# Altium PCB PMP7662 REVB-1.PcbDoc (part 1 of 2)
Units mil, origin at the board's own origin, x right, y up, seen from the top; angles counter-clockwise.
Board outline 7874.02 x 3937.01 mil, 2 copper layers (Top Layer, Bottom Layer), stack 62 mil thick; 165 components, 77 nets, 359 pads, 90 vias.
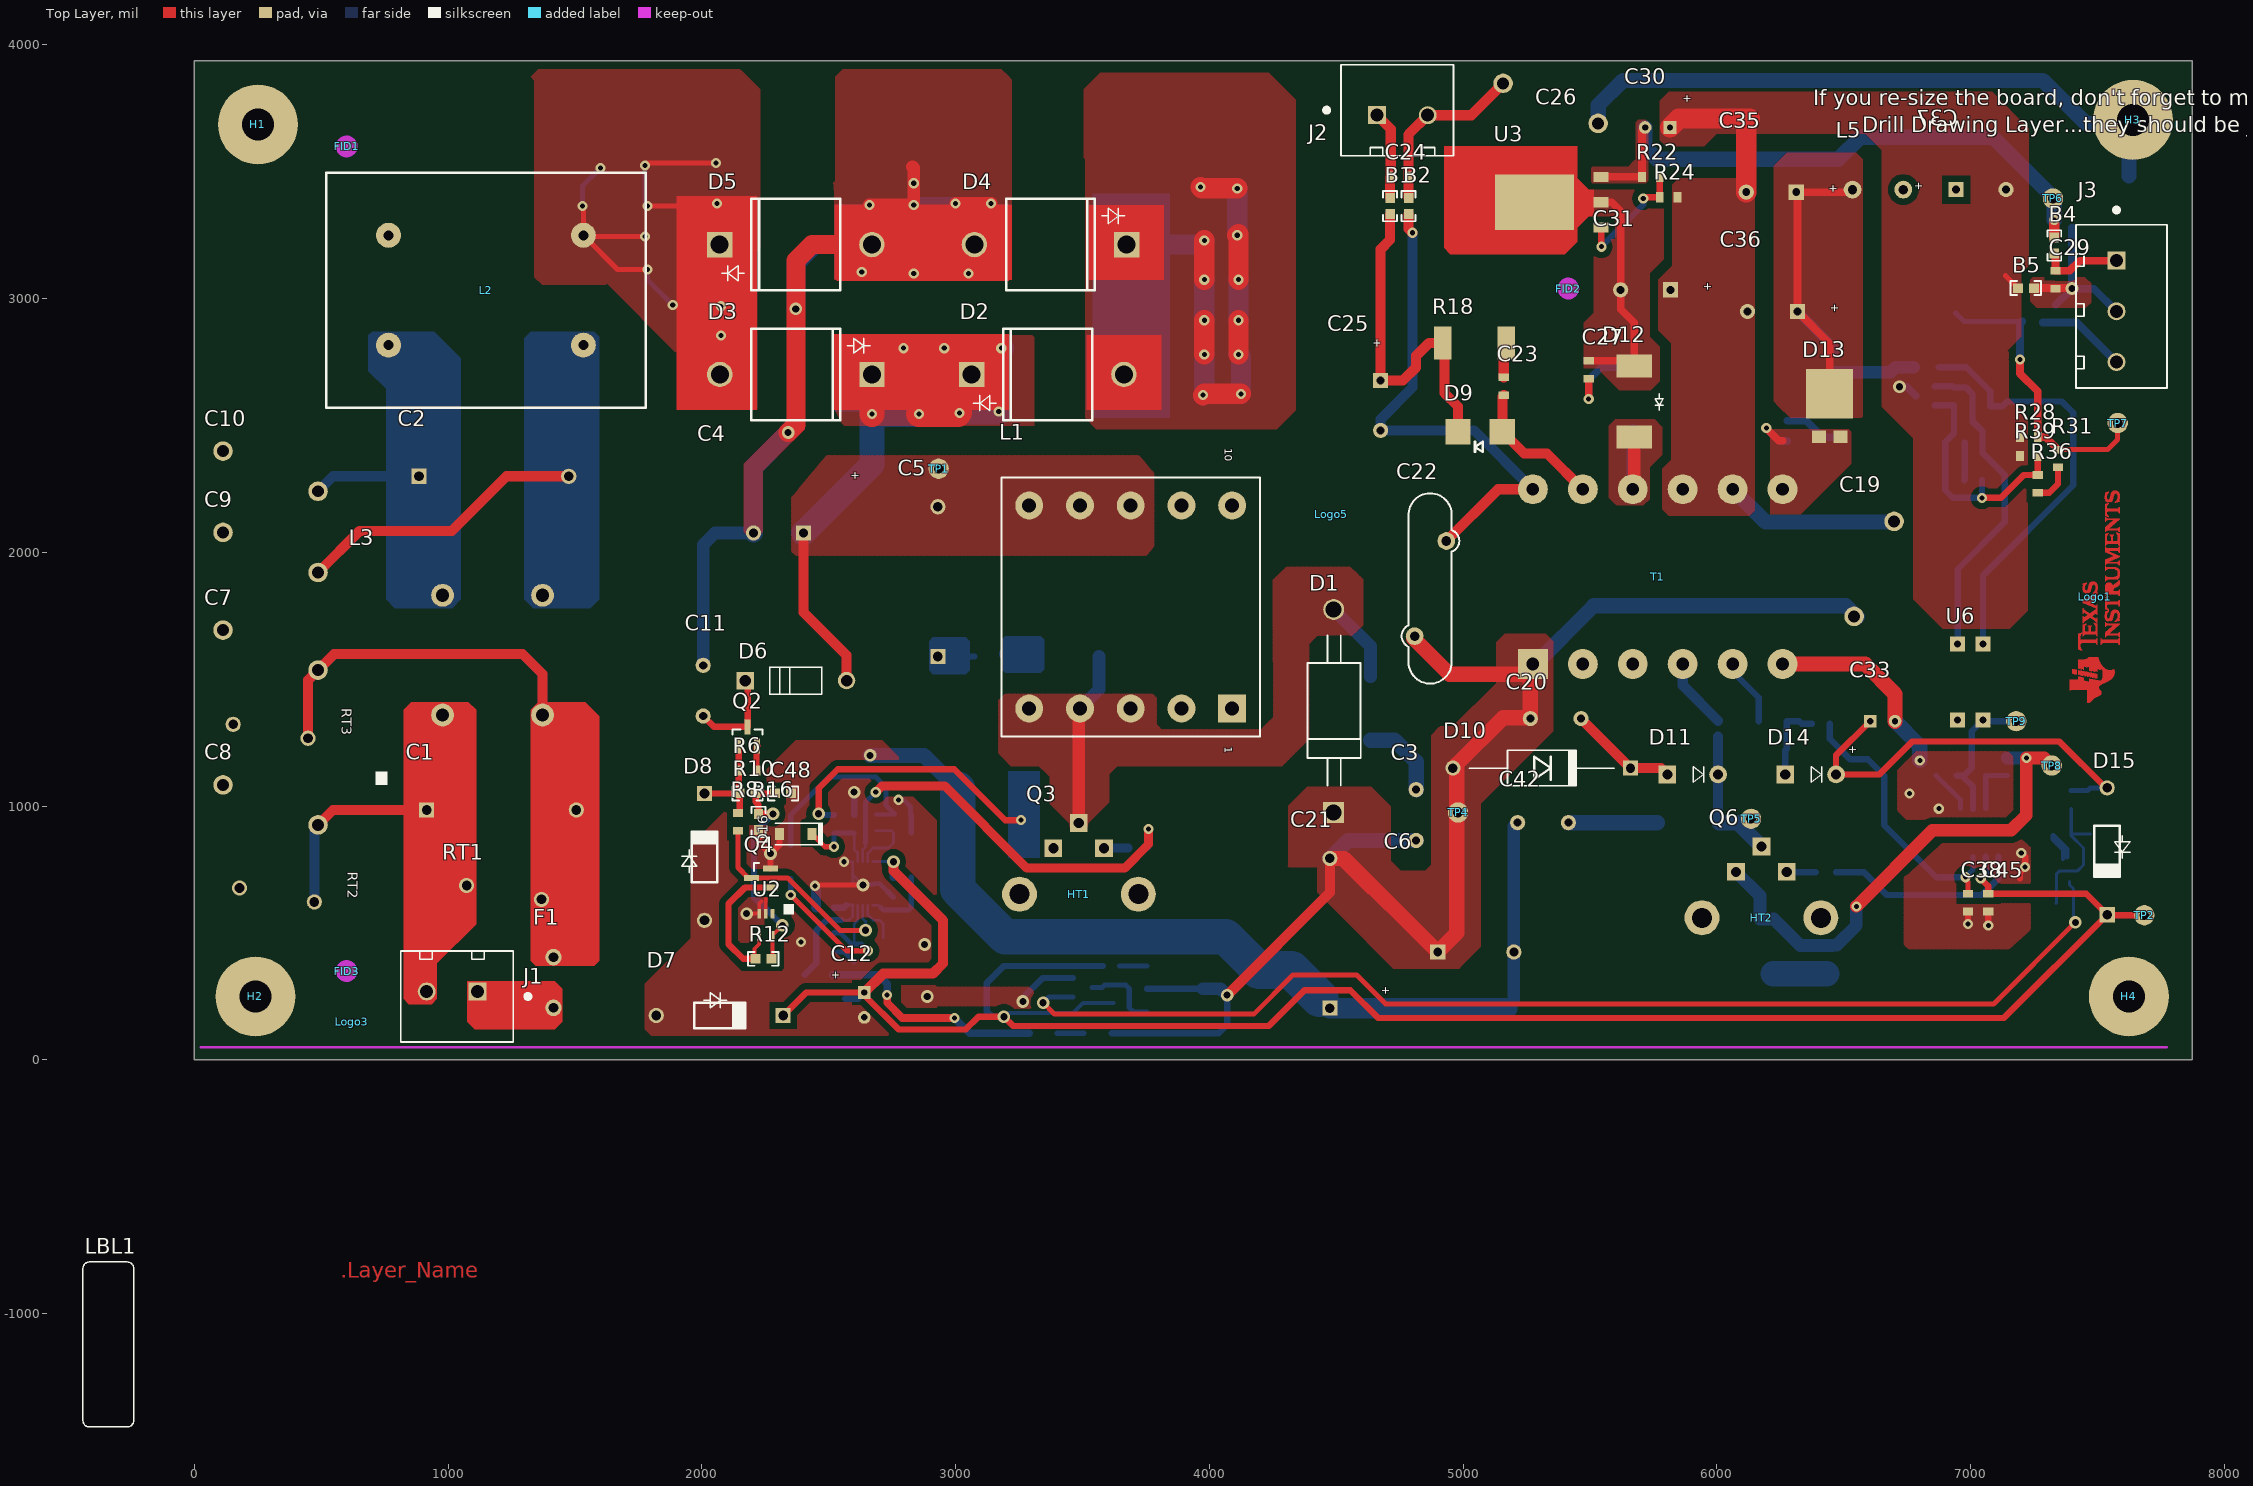
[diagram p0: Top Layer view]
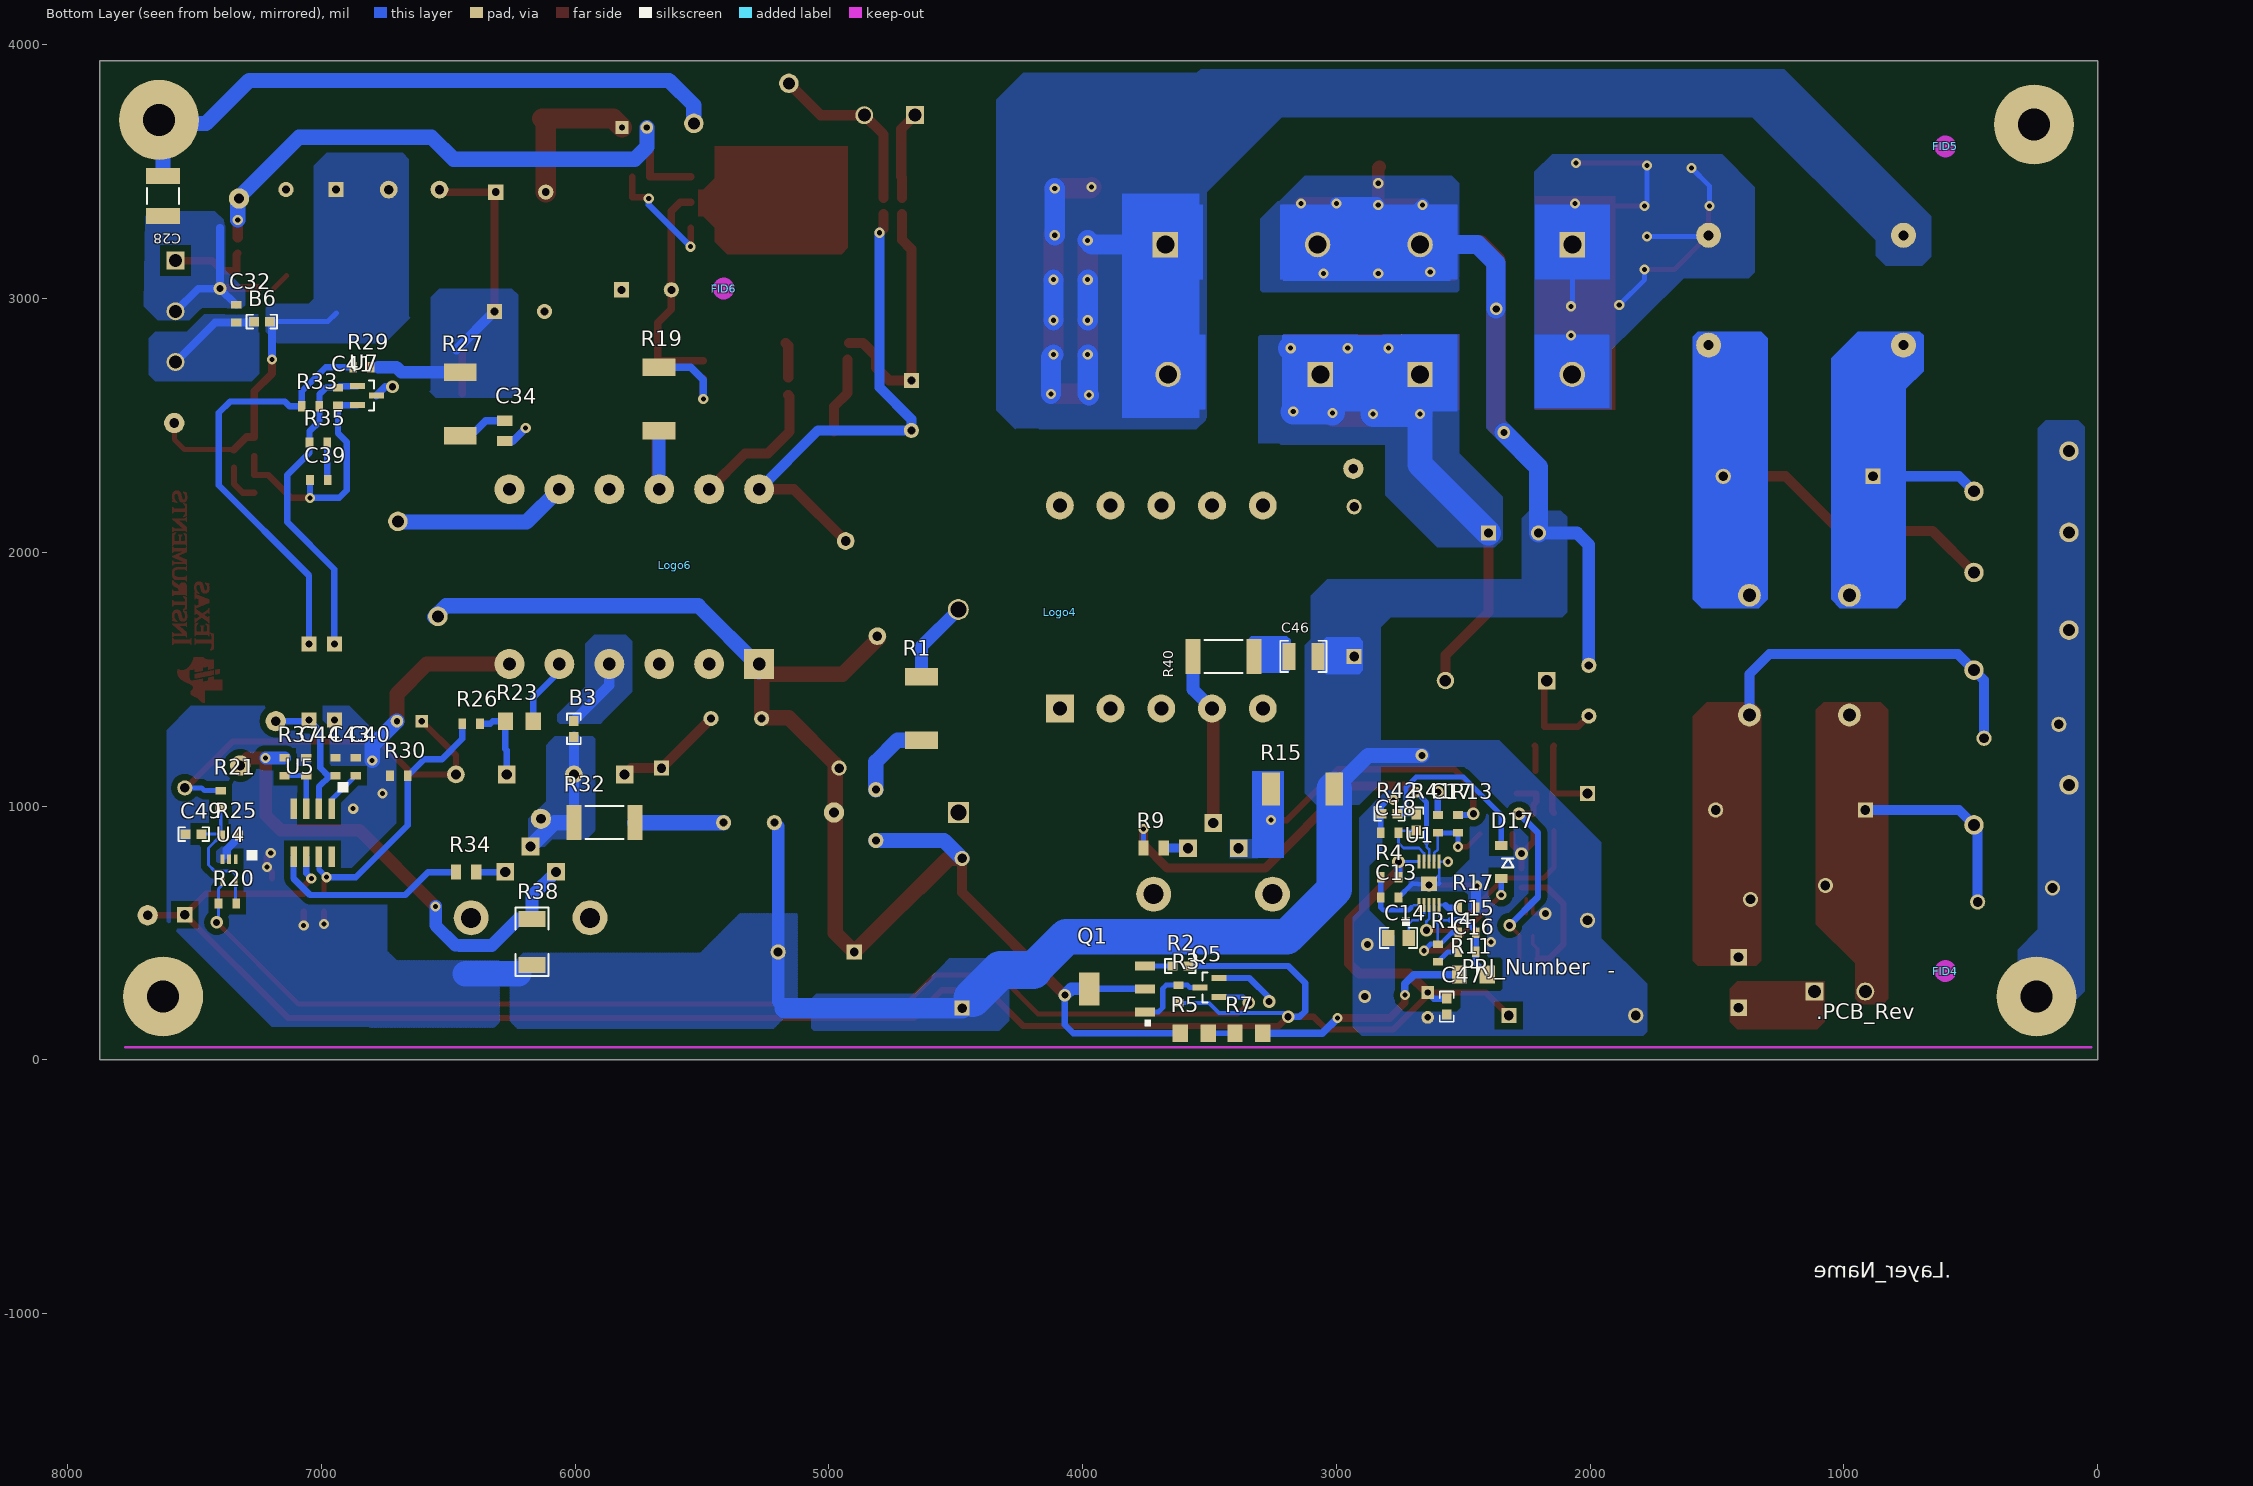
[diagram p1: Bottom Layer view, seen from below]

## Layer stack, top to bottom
Top Layer: signal copper 1.4
Dielectric: core 59.2, FR-4, Dk 4.8
Bottom Layer: signal copper 1.4

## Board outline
0,0 7874.02,0 7874.02,3937.01 0,3937.01

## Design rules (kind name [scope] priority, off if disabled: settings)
AcuteAngle [All] p1: minimum=4.50000000000000E+0001 checktracksonly=FALSE
AssemblyTestPointUsage [All] p1: valid=2
Clearance Clearance_TH [IsVia vs IsThruPin] p1: gap=15
Clearance "Clearance_SMT to Via" [IsSMTPin vs IsVia] p2: gap=15
Clearance "Clearance_Via to Via" [IsVia vs IsVia] p3: gap=12
Clearance "Clearance_Poly to Poly" [InPolygon vs InPolygon] p4: gap=25
Clearance Clearance_Poly [InPolygon] p5: gap=25
Clearance [All] p6: gap=8
ComponentClearance ComponentClearance_Logo [InComponentClass('Logo')] p1: gap=50 collisioncheckmode=3 verticalgap=10 showdistances=FALSE
ComponentClearance ComponentClearance_ScrewToNut [(HasFootprint('NY PMS 440 0025 PH')) vs (HasFootprint('Keystone_1902C'))] p2: gap=5 collisioncheckmode=3 verticalgap=10 showdistances=FALSE
ComponentClearance ComponentClearance_MountingHoles [InComponentClass('Mounting Holes')] p3: gap=250 collisioncheckmode=3 verticalgap=100000 showdistances=FALSE
ComponentClearance ComponentClearance_SmallPassives [HasFootprint('0201*') or HasFootprint('0402*') or HasFootprint('0508') or HasFootprint('0603*') or HasFootprint('0612') or HasFootprint('0805*') or HasFootprint('0815*') or HasFootprint('0830*') or HasFootprint('1206*') or HasFootprint('1210*') or HasFootprint('1808*') or HasFootprint('1812*') or HasFootprint('1825*') or HasFootprint('2010*') or HasFootprint('2220*') or HasFootprint('2225*') or HasFootprint('2512*') or HasFootprint('2728*') or HasFootprint('3518*') vs HasFootprint('0201*') or HasFootprint('0402*') or HasFootprint('0508') or HasFootprint('0603*') or HasFootprint('0612') or HasFootprint('0805*') or HasFootprint('0815*') or HasFootprint('0830*') or HasFootprint('1206*') or HasFootprint('1210*') or HasFootprint('1808*') or HasFootprint('1812*') or HasFootprint('1825*') or HasFootprint('2010*') or HasFootprint('2220*') or HasFootprint('2225*') or HasFootprint('2512*') or HasFootprint('2728*') or HasFootprint('3518*')] p4: gap=20 collisioncheckmode=3 verticalgap=10 showdistances=FALSE
ComponentClearance ComponentClearance_THtoSMT [IsThruComponent vs IsSMTComponent] p5: gap=100 collisioncheckmode=3 verticalgap=30 showdistances=FALSE
ComponentClearance ComponentClearance_THtoTH [IsThruComponent vs IsThruComponent] p6: gap=118.11 collisioncheckmode=3 verticalgap=30 showdistances=FALSE
ComponentClearance [All] p7: gap=40 collisioncheckmode=3 verticalgap=10 showdistances=FALSE
DiffPairsRouting [All] p1: maxlimit=100 minlimit=10 mostfreqgap=10 maxuncoupledlength=1000
FabricationTestPointUsage TestPointUsage [All] p1: valid=2 allowmultiple=FALSE
FabricationTestpoint Testpoint [All] p1: side=3 testpointundercomponent=TRUE minsize=40 maxsize=100 preferedsize=60 minholesize=0 maxholesize=40 preferedholesize=32 testpointgrid=1 allowsidetop=TRUE allowsidebottom=TRUE usegrid=TRUE gridtolerance=0.01
FanoutControl Fanout_LCC [IsLCC] p1: bgadir=Out bgaviamode=Centered fanoutstyle=Auto fanoutdirection=Alternating viagrid=1 // Fanout_LCC (Default Rule)
FanoutControl Fanout_BGA [IsBGA] p2: bgadir=Out bgaviamode=Centered fanoutstyle=Auto fanoutdirection=Alternating viagrid=1 // Fanout_BGA (Default Rule)
FanoutControl Fanout_Default [All] p4: bgadir=Out bgaviamode=Centered fanoutstyle=Auto fanoutdirection=Alternating viagrid=1 // Fanout_Default (Default Rule)
FanoutControl Fanout_Small [(CompPinCount < 5)] p5: bgadir=Out bgaviamode=Centered fanoutstyle=Auto fanoutdirection=OutThenIn viagrid=1 // Fanout_Small (Default Rule)
HoleSize [All] p1: absolutevalues=TRUE maxlimit=251 minlimit=8 maxpercent=80.000 minpercent=20.000
MinimumAnnularRing MinimumAnnularRing_ThermalPadVias [IsVia and InAnyComponent] p1: minimumring=5.91
MinimumAnnularRing [All] p2: minimumring=9
MinimumSolderMaskSliver MinimumSolderMaskSliver_Logo [InComponentClass('Logo') vs InComponentClass('Logo')] p1: minsoldermaskwidth=0.7
MinimumSolderMaskSliver [All] p2: minsoldermaskwidth=3.94
PlaneConnect [All] p1: planeconnectstyle=Relief reliefexpansion=10 reliefentries=4 reliefconductorwidth=10 reliefairgap=10
PolygonConnect [All] p1: connectstyle=Direct reliefconductorwidth=20 reliefentries=4 polygonreliefangle="45 Angle" airgapwidth=10
RoomDefinition Hardware [InComponentClass('Hardware')] p1: confinementstyle=ConfineIn formatcopy=TRUE lockcomponents=FALSE outline -692,-1534 1308,-1534 1308,-534 -692,-534
RoomDefinition "Fly back converter" [InComponentClass('Fly back converter')] p2: confinementstyle=ConfineIn formatcopy=TRUE lockcomponents=FALSE outline -692,-1534 1308,-1534 1308,-534 -692,-534
RoomDefinition "Boost converter" [InComponentClass('Boost converter')] p3: confinementstyle=ConfineIn formatcopy=TRUE lockcomponents=FALSE outline -692,-1534 1308,-1534 1308,-534 -692,-534
RoutingVias ThermalPadVias [IsVia and InAnyComponent] p1: holewidth=20 width=40 viastyle="Through Hole" minholewidth=16 minwidth=30 maxholewidth=20 maxwidth=40
RoutingVias [All] p2: holewidth=20 width=40 viastyle="Through Hole" minholewidth=20 minwidth=40 maxholewidth=40 maxwidth=65
SMDToCorner [All] p1: distance=30000
SilkToSilkClearance [All] p1: silktosilkclearance=5
SilkscreenOverComponentPads [All] p1: minsilkscreentomaskgap=5
SolderMaskExpansion [All] p1: expansion=2
Width [All] p1: maxlimit=200 minlimit=10 preferedwidth=20 checkconnectedcopper=TRUE
14 further rules are at their usual default settings.

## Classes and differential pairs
component class hardware: !PCB1 FID1 FID2 FID3 FID4 FID5 FID6 H1 H2 H3 H4 LBL1 Logo1
component class "Boost converter": C1 C2 C3 C4 C5 C6 C7 C8 C9 C10 C11 C12 C13 C14 C15 C16 C17 C18 C46 C47 C48 D1 D2 D3 D4 D5 D6 D7 D8 D16 D17 F1 HT1 J1 L1 L2 L3 Q1 Q2 Q3 Q4 R1 R2 R3 R4 R5 R6 R7 R8 R9 R10 R11 R12 R13 R14 R15 R16 R17 R40 R41 R42 RT1 RT2 RT3 TP1 TP2 U1 U2
component class "Fly back converter": B1 B2 B3 B4 B5 B6 C19 C20 C21 C22 C23 C24 C25 C26 C27 C28 C29 C30 C31 C32 C33 C34 C35 C36 C37 C38 C39 C40 C41 C42 C43 C44 C45 C49 D9 D10 D11 D12 D13 D14 D15 HT2 J2 J3 J7 J8 J9 L5 Q5 Q6 R18 R19 R20 R21 R22 R23 R24 R25 R26 R27 R28 R29 R30 R31 R32 R33 R34 R35 R36 R37 R38 R39 T1 TP4 TP5 TP6 TP7 TP8 TP9 U3 U4 U5 U6 U7

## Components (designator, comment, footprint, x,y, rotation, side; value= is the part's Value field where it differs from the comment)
B1 "BEAD-BLM18AG_SERIES" 0603 4712,3365 r90 top
B2 "BEAD-BLM18AG_SERIES" 0603 4785,3365 r90 top
B3 "CIS10P700AC" 0603 6005,1305 r90 bottom
B4 "BEAD-BLM18AG_SERIES" 0603 7330,3210 r270 top
B5 "BEAD-BLM18AG_SERIES" 0603 7218,3042 r0 top
B6 "BEAD-BLM18AG_SERIES" 0603 7235,2910 r0 bottom
C1 "R46KI347050P1M" CAP_591MIL 915,985 r0 top
C2 "R46KI347050P1M" CAP_591MIL 885,2300 r0 top
C3 "CAP_DE2B3K_7MM_SERIES" CAP_200MIL-A 4815,965 r90 top
C4 "CAP_EEU-FC1E16_20MM" CAP_16MM_DIA_ 2300,2080 r270 top
C5 "R46KI347050P1M" CAP_591MIL 2930,1590 r90 top
C6 "CAP_EEU-FC18_25MM" CAP_EEUFC1H 5055,425 r90 top
C7 "CAP_DISK_440_[8.4MM]" CAP_DISK_8.4MM 300,1615 r180 top
C8 "CAP_DISK_440_[8.4MM]" CAP_DISK_8.4MM 300,1005 r180 top
C9 "VY2222M35Y5US63V7" CAP_DISK_8.4MM 300,2000 r180 top
C10 "VY2222M35Y5US63V7" CAP_DISK_8.4MM 300,2320 r180 top
C11 "CAP_ECU-S1HXXKBB" CAP_200MIL 2005,1455 r270 top
C12 "CAP_ZL_6.3MM_SERIES" CAP_ZL-6.3MM 2640,215 r0 top
C13 "C603" C603 2790,640 r0 bottom
C14 "C2012X5R1C226K125AC" 0805_HV 2755,481 r0 bottom
C15 "C603" C603 2485,501 r0 bottom
C16 "C603" C603 2485,426 r180 bottom
C17 "C603" C603 2600,930 r270 bottom
C18 "C603" C603 2790,895 r180 bottom
C19 "VY2222M35Y5US63V7" CAP_DISK_8.4MM 6620,1935 r90 top
C20 "CAP_ECU-S1HXXKBB" CAP_200MIL 5365,1345 r180 top
C21 "R46KI347050P1M" CAP_591MIL 4475,204 r90 top
C22 "CAP_DISK_720" CAP_DISK_720 4935,2045 r270 top
C23 "C603" c603 5160,2655 r90 top
C24 "C603" C603 4750,3481 r0 top
C25 "CAP_EKZE_10MM_SERIES" CAP_ALUM-10MM#1 4675,2680 r0 top
C26 "VY2222M35Y5US63V7" CAP_DISK_8.4MM 5345,3770 r0 top
C27 "C603" C603 5495,2720 r270 top
C28 "1812GC472KAT1A" 1812 7625,3405 r270 bottom
C29 "C603" C603 7335,3075 r270 top
C30 "CAP_ZL_6.3MM_SERIES" CAP_ZL-6.3MM 5765,3675 r270 top
C31 "CAP_EKZE_10MM_SERIES" CAP_ALUM-10MM#1 5820,3035 r270 top
C32 "C603" C603 7336,2941 r270 bottom
C33 "CAP_ZL_6.3MM_SERIES" CAP_ZL-6.3MM 6655,1335 r90 top
C34 "C0805" C0805 6278,2479 r270 bottom
C35 "CAP_EKZE_10MM_SERIES" CAP_ALUM-10MM#1 6315,3420 r270 top
C36 "CAP_EKZE_10MM_SERIES" CAP_ALUM-10MM#1 6320,2950 r270 top
C37 "CAP_ALUM_FC-F" CAP_ALUM-10MM#2 6941,3430 r270 top
C38 "C603" C603 6990,620 r270 top
C39 "C603" C603 7010,2285 r180 bottom
C40 "C603" c603 6865,1155 r270 bottom
C41 "C603" C603 6935,2614 r270 bottom
C42 "CAP_DE2B3K_7MM_SERIES" CAP_200MIL-A 5315,935 r180 top
C43 "C603" c603 6945,1155 r90 bottom
C44 "C603" c603 7060,1155 r90 bottom
C45 "C603" c603 7070,620 r90 top
C46 "GRM32QR73A103KW01L" 1210 3130,1590 r180 bottom
C47 "GRM188R71C683KA01D" 0603 2565,210 r270 bottom
C48 "GRM188R71C683KA01D" 0603 2320,1050 r0 top
C49 "GRM188R71C683KA01D" 0603 7503.5,890 r0 bottom
D1 "D-MUR4XX_SERIES" DO-201AD 4490,1375 r90 top
D2 "D-6A0X" R-6 3063,2701.5 r0 top
D3 "D-6A0X" R-6 2670.32,2701.5 r180 top
D4 "D-6A0X" R-6 3674,3213.31 r180 top
D5 "D-6A0X" R-6 2070,3213.31 r0 top
D6 "D-1N4006" DO-41 2370,1495 r0 top
D7 "D-1N52XXB" DO-35 2320,175 r180 top
D8 "D-1N52XXB" DO-35 2010,1050 r270 top
D9 "D_SCHOT_SMB" MOT_SMB_CASE 5067,2476 r0 top
D10 "D_P6KEXXX" DO-204AC 5310,1150 r180 top
D11 "D-1N4006" DO-41_VERT 5805,1125 r0 top
D12 "D-ES3D" DO-214AB 5675,2595 r90 top
D13 "D-S4P_SERIES" TO-277[SMPC] 6445,2625 r0 top
D14 "D-1N4006" DO-41_VERT 6270,1125 r0 top
D15 "D-1N4148MSCT" DO-35 7538.5,572 r90 top
D16 "1N5819HW-7-F" SOD-123 2370,890 r180 top
D17 "D-1N4148-7-F" D_SOD123 2350,780 r90 bottom
F1 "FUSE_RST_SERIES" FUSE_4X8.5-5.08P 1415,205 r90 top
FID1 "Fiducial" Fiducial10-20 600,3600 r0 top
FID2 "Fiducial" Fiducial10-20 5415,3040 r0 top
FID3 "Fiducial" Fiducial10-20 600,350 r0 top
FID4 "Fiducial" Fiducial10-20 600,350 r180 bottom
FID5 "Fiducial" Fiducial10-20 600,3600 r180 bottom
FID6 "Fiducial" Fiducial10-20 5415,3040 r180 bottom
H1 "" "NY PMS 440 0025 PH" 250,3687.01 r0 top locked
H2 "" "NY PMS 440 0025 PH" 240,250 r90 top
H3 "" "NY PMS 440 0025 PH" 7640,3705 r90 top
H4 "" "NY PMS 440 0025 PH" 7624.02,250 r0 top locked
HT1 "HEATSINK_PMP1445-HS4" R2A-CT2-38E-ND 3720,653 r180 top
HT2 "HEATSINK_PMP1445-HS4" R2A-CT2-38E-ND 6410,560 r180 top locked
J1 "OSTTA024163" On-Shore_OSTTA024163 1035,250 r180 top
J2 "OSTTA024163" On-Shore_OSTTA024163 4741,3743 r0 top
J3 "OSTTA034163" On-Shore_OSTTA034163 7595,2970 r270 top
L1 "IND_EF25_10P" IND_EF25_10P 4090,1385 r270 top
L2 "SS30V-R350047" SS30V 765,3250 r0 top
L3 "1.0mH" IND_WE_728_X_1083 1175,1595 r90 top
L5 "2.2uH" IND_200_MIL 6635,3430 r0 top
LBL1 "" Label_650x200 -339.5,-1121.5 r90 top
Logo1 "" TI_Stacked_SolderMask_Small 7490,1825 r90 top
Logo3 "DANGER HIGH VOLTAGE" IEC_HighVoltage_Small 620,150 r0 top
Logo4 "DANGER HIGH VOLTAGE" IEC_HighVoltage_Small 4090,1765 r180 bottom (schematic designator Logo3)
Logo5 "DANGER HIGH VOLTAGE" IEC_HighVoltage_Small 4480,2150 r0 top (schematic designator Logo3)
Logo6 "DANGER HIGH VOLTAGE" IEC_HighVoltage_Small 5607.88,1950 r180 bottom (schematic designator Logo3)
Q1 "TR_NFET_SOT223" TR_SOT223 3865,280 r90 bottom
Q2 "TR-BSS126" SOT-23 2180,1275 r90 top
Q3 "TR-FQPF2N60C" TO-220V 3585,834.1 r180 top locked
Q4 "TR-2N7002" SOT-23 2233,717 r180 top
Q5 "TR-2N7002" SOT-23 3500,285 r0 bottom
Q6 "TR-FQPF2N60C" TO-220V 6275.75,741.1 r180 top
R1 "R2512" R2512 4635,1385 r270 bottom
R2 "RC0603FR-07220RL" 0603 3615,370 r0 bottom
R3 "R603" R603 3621.57,259.3 r270 bottom
R4 "R603" R603 2790,720 r0 bottom
R5 "R1206" R1206 3560,105 r180 bottom
R6 "R603" R603 2180,1140 r180 top
R7 "R1206" R1206 3345,105 r180 bottom
R8 "R603" R603 2142,938 r270 top
R9 "R0805_1%" R0805 3720,835 r180 bottom
R10 "CRCW0603402KFKEA" 0603 2180,1050 r0 top
R11 "R1206" r1206 2460,336 r180 bottom
R12 "CRCW06031M00FKEA" 0603 2242,398 r180 top
R13 "R603" R603 2520,930 r90 bottom
R14 "R603" R603 2600,421 r270 bottom
R15 "R2512_1%" R2512 3133,1067 r180 bottom
R16 "CRCW0603127KFKEA" 0603 2223,938 r270 top
R17 "R603" R603 2485,600 r180 bottom
R18 "R2512" R2512 5045,2825 r180 top
R19 "R2512" R2512 5670,2605 r270 bottom
R20 "R603" r603 7371,617 r0 bottom
R21 "R603" r603 7397,1026 r90 bottom
R22 "R603" R603 5740,3480 r180 top
R23 "R1206" R1206 6220,1335 r0 bottom
R24 "R603" R603 5810,3400 r0 top
R25 "R603" r603 7360,885 r180 bottom
R26 "R603" r603 6410,1325 r0 bottom
R27 "R2512" R2512 6453,2585 r90 bottom
R28 "R603" R603 7230,2455 r180 top
R29 "R603" R603 6840,2730 r180 bottom
R30 "R603" r603 6695,1120 r0 bottom
R31 "R603" R603 7345,2370 r90 top
R32 "CRCW2512162RFKEGHP" 2512M 5885,935 r0 bottom
R33 "R603" R603 7043,2576 r180 bottom
R34 "R0805_1%" r0805 6430,740 r180 bottom
R35 "R603" R603 7012,2433 r180 bottom
R36 "R603" R603 7265,2270 r90 top
R37 "R603" r603 7145,1155 r90 bottom
R38 "R2010" 2010 6170,465 r270 bottom
R39 "R603" R603 7230,2380 r180 top
R40 "RHC2512FT68R0" 2512M 3445,1590 r0 bottom
R41 "RC0603FR-0727KL" 0603 2685,935 r270 bottom
R42 "RC0603FR-074K3L" 0603 2790,970 r180 bottom
RT1 "MOV_B72210SXXXXK101" DISK-472 1220,660 r0 top
RT2 "MOV_B72210SXXXXK101" DISK-472 325,650 r0 top
RT3 "MOV_B72210SXXXXK101" DISK-472 300,1295 r0 top
T1 "EI-30" XFMR-EI30-10PIN-VER-TEMP 5275,1560 r90 top
TP1 "TESTPOINT" TESTPOINT 2933,2330 r0 top
TP2 "TESTPOINT" TESTPOINT 7685,570 r0 top
TP4 "TESTPOINT" TESTPOINT 4980,975 r0 top
TP5 "TESTPOINT" TESTPOINT 6135,950 r0 top
TP6 "TESTPOINT" TESTPOINT 7325,3395 r0 top
TP7 "TESTPOINT" TESTPOINT 7580,2510 r0 top
TP8 "TESTPOINT" TESTPOINT 7320,1160 r0 top
TP9 "TESTPOINT" TESTPOINT 7180,1335 r0 top
U1 "TPS40210DGQ" DGQ_10PWP 2634.8,694.5 r90 bottom
U2 "LMS33460" SC-70-5 2252,533 r180 top
U3 "LM337KTER" KTE 5280,3380 r90 top
U4 "LMS33460" SC-70-5 7364,747 r0 bottom
U5 "UCC28600DR" SO8 7035,895 r270 bottom
U6 "LTV-817A" DIP-4A 7050,1640 r270 top
U7 "TL431AIDBZ" SOT-23 6821,2618 r180 bottom

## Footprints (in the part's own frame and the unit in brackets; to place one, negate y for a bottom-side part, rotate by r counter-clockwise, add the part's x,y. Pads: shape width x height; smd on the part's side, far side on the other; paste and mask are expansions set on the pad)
0603 [mm] "0603 from SM-752 data"
  rect 1x0.95 smd: 1(-0.8,0) 2(0.8,0)
  silkscreen extent -1.52,-0.69 1.52,0.69, body extent -0.87,-0.47 0.87,0.47, height 0.85
0805_HV [mil] "0805 with 30mil clearance between pads"
  rect 50x63 smd: 1(-40,0) 2(40,0)
  silkscreen extent -74,-40 74,40, body extent -43,-29 43,29, height 43
1210 [mm] "1210 from SM-752 data"
  rect 1.3x2.7 smd: 1(-1.45,0) 2(1.45,0)
  silkscreen extent -2.32,-1.57 2.32,1.57, body extent -1.7,-1.35 1.7,1.35, height 1.35
1812 [mm]
  rect 1.6x3.4 smd: 1(-2,0) 2(2,0)
  silkscreen extent -0.8,-1.6 0.8,1.6, body extent -2.4,-1.7 2.4,1.7, height 1.35
2010 [mm] "Chip Capacitor, Body 5.08x2.54mm, IPC Medium Density"
  rect 1.6x2.7 smd: 1(-2.3,0) 2(2.3,0)
  silkscreen extent -3.42,-1.65 3.42,1.65, body extent -2.73,-1.45 2.73,1.45, height 1.66
2512M [mm] "Chip Resistor, Body 6.3x3.2mm, IPC Low Density"
  rect 1.5x3.5 smd: 1(-3.05,0) 2(3.05,0)
  silkscreen extent -1.9,-1.65 1.9,1.65, body extent -3.22,-1.67 3.22,1.67, height 0.71
C603 [mil]
  rect 30x40 smd mask+2: 1(-35,0) 2(35,0)
c603 [mil]
  rect 30x40 smd mask+2: 1(-35,0) 2(35,0)
C0805 [mil]
  rect 40x60 smd: 1(-40,0) 2(40,0)
CAP_16MM_DIA_ [mil]
  rect 60x60 hole 35 mask+5: 1(3.4,100.6)
  round 60 hole 35 mask+5: 2(3.4,-96.4)
CAP_200MIL [mil]
  round 60 hole 32 mask+5: 1(-100,0) 2(100,0)
CAP_200MIL-A [mil]
  round 60 hole 32: 1(-100,0) 2(100,0)
CAP_591MIL [mil]
  rect 60x60 hole 38: 1(0,0)
  round 60 hole 38: 2(590,0)
CAP_ALUM-10MM#1 [mil]
  rect 60x60 hole 31: 1(0,-2)
  round 60 hole 31: 2(0,-199)
CAP_ALUM-10MM#2 [mil]
  rect 60x60 hole 31: 1(0,2)
  round 60 hole 31: 2(0,199)
CAP_DISK_8.4MM [mil]
  round 77 hole 47: 1(-187,79) 2(187.5,-79)
CAP_DISK_720 [mil]
  round 70 hole 38: 1(0,-1) 2(375,-126)
  silkscreen extent -188,-177 562,50
CAP_EEUFC1H [mil]
  rect 60x60 hole 35: 1(0.1,155)
  round 60 hole 35: 2(0,-145)
CAP_ZL-6.3MM [mil]
  rect 50x50 hole 25: 1(0,50.5)
  round 50 hole 25: 2(0,-47.5)
D_SOD123 [mil]
  rect 36x48 smd: 1(65,0) 2(-65,0)
  silkscreen extent -21,-48 14,-3
DGQ_10PWP [mil]
  rect 55x11 smd: 1(-84.5,39) 2(-84.5,19.3) 3(-84.5,-0.4) 4(-84.5,-20.1) 5(-84.5,-39.8) 6(86.5,-39.8) 7(86.5,-20.1) 8(86.5,-0.4) 9(86.5,19.3) 10(86.5,39)
  rect 57.87x61.81 smd: 11(0,0)
  silkscreen extent -165,75 -135,105
DIP-4A [mil]
  rect 60x60 hole 28: 1(0.5,-1) 2(0.5,-101) 3(300.5,-101) 4(300.5,-1)
DISK-472 [mil]
  round 60 hole 38: 1(-147.5,27.5) 2(147.5,-27.5)
DO-35 [mil]
  rect 60x60 hole 38: 1(0,0)
  round 60 hole 38: 2(500,0)
  silkscreen extent 150,-90 350,51
DO-41 [mm] "diode"
  rect 1.75x1.75 hole 1.15: 1(-5.08,0)
  round 1.75 hole 1.15: 2(5.08,0)
  silkscreen extent -2.62,-1.37 2.59,1.35, body extent -5.51,-1.36 5.51,1.36, height 2.72
DO-41_VERT [mil]
  rect 70x70 hole 40: 1(0,0)
  round 70 hole 40: 2(200,0)
  silkscreen extent 103,-30 143,30
DO-201AD [mm] "Vishay dimensions"
  rect 2.1x2.1 hole 1.6: 1(-10.16,0)
  round 2.1 hole 1.6: 2(10.16,0)
  silkscreen extent -7.47,-2.7 7.57,2.61, body extent -10.82,-2.68 10.82,2.61, height 5.3
DO-204AC [mil]
  rect 60x60 hole 37: 1(-350,0)
  round 60 hole 37: 2(350,0)
  silkscreen extent -285,-70 285,70
DO-214AB [mil]
  rect 90x140 smd: 1(-140,0) 2(140,0)
  silkscreen extent -35,-113 30,-83
Fiducial10-20 [mm]
  round 1 smd paste+0 mask+0.5: 1(0,0)
  Top Layer keep-out circle w1.178: c0,0 r0.5
FUSE_4X8.5-5.08P [mil]
  round 65 / inner rect 65x65 / far side rect 65x65 hole 38: 1(0,0) 2(200,0)
IEC_HighVoltage_Small [mil]
IND_200_MIL [mil]
  round 70 hole 37: 1(-100,0) 2(100,0)
IND_EF25_10P [mil]
  rect 110x110 hole 55: 1(0,0)
  round 110 hole 55: 2(0,-200) 3(0,-400) 4(0,-600) 5(0,-800) 6(-800,-800) 7(-800,-600) 8(-800,-400) 9(-800,-200) 10(-800,0)
  silkscreen extent -910,-910 110,110
IND_WE_728_X_1083 [mil]
  round 90 hole 52: 2(-236,197) 4(-236,-197) 7(236,-197) 9(236,197)
  silkscreen extent -510,415 -460,460
KTE [mil]
  rect 40x60 smd: 1(-100,-264) 2(0,-264) 3(100,-264)
  rect 220x310 smd: 4(0,-1.7)
Label_650x200 [mil] "Thermal Transfer Label"
  round 1 on Mech13: 0(0,0)
  silkscreen extent -325,-100 325,100, body extent -326,-101 326,101, height 1
MOT_SMB_CASE [mil]
  rect 100x100 smd: 1(-87,0) 2(88,0)
  silkscreen extent -20,-80 10,-40
"NY PMS 440 0025 PH" [mm] "4-40 nylon screw and mounting hole"
  round 8 hole 3.2: 1(0,0)
  body extent -3.3,-3.3 3.3,3.3, height 2.69
On-Shore_OSTTA024163 [mm] "TERM BLOCK 2x1, 5.08mm, TH"
  rect 1.8x1.8 hole 1.3: 1(-2.04,-0.5)
  round 1.8 hole 1.3 paste+0: 2(3.04,-0.5)
  silkscreen extent -7.18,-4.55 5.63,4.55, body extent -5.68,-4.6 5.68,4.6, height 13
On-Shore_OSTTA034163 [mm] "TERM BLOCK 3x1, 5.08mm, TH"
  rect 1.8x1.8 hole 1.3: 1(-4.58,-0.5)
  round 1.8 hole 1.3 paste+0: 2(0.5,-0.5) 3(5.58,-0.5)
  silkscreen extent -9.73,-4.55 8.17,4.55, body extent -8.22,-4.6 8.22,4.6, height 13
R2A-CT2-38E-ND [mm] "HEATSINK FOR TO-220"
  round 3.5 hole 2: 1(0,0) 2(11.9,0)
R603 [mil]
  rect 30x40 smd: 1(-35,0) 2(35,0)
r603 [mil]
  rect 30x40 smd: 1(-35,0) 2(35,0)
R0805 [mil]
  rect 40x60 smd: 1(-40,0) 2(40,0)
r0805 [mil]
  rect 40x60 smd: 1(-40,0) 2(40,0)
R1206 [mil]
  rect 60x70 smd: 1(-55,0) 2(55,0)
r1206 [mil]
  rect 60x70 smd: 1(-55,0) 2(55,0)
R2512 [mil]
  rect 70x130 smd: 1(-125,0) 2(125,0)
R-6 [mil]
  rect 100x100 hole 71: 1(0,0)
  round 100 hole 71: 2(600,0)
  silkscreen extent 7,-180 475,180
SC-70-5 [mil]
  rect 15x38 smd: 1(-25.9,-43.4) 2(0.1,-43.4) 3(26.1,-43.4) 4(26.1,43.6) 5(-25.9,43.6)
  silkscreen extent -110,-80 -70,-40
SO8 [mil]
  rect 80x26 smd: 1(-95,75) 2(-95,25) 3(-95,-25) 4(-95,-75) 5(94,-75) 6(94,-25) 7(94,25) 8(94,75)
  silkscreen extent -200,100 -160,140
SOD-123 [mm] "On Semi recommended land pattern"
  rect 0.915x1.22 smd: 1(-1.637,0) 2(1.637,0)
  silkscreen extent -2.74,-1.17 2.03,1.17, body extent -1.93,-0.9 1.93,0.9, height 1.35
SOT-23 [mm] "SOT23, 3-Leads, Body 2.9x1.3mm, Pitch 0.95mm, Lead Span 2.5mm, IPC Medium Density"
  rect 1.5x0.6 smd: 1(-0.95,0.95) 2(-0.95,-0.95) 3(0.95,0)
  silkscreen extent 0.2,-1.5 0.7,1.5, body extent -1.16,-1.45 1.21,1.45, height 1
SS30V [mm]
  round 2.5 hole 1: 1(0,0) 2(19.5,0) 3(19.5,-11) 4(0,-11)
  silkscreen extent -6.25,-17.25 25.75,6.25
TESTPOINT [mil]
  round 80 hole 37.99: 1(0,0)
TI_Stacked_SolderMask_Small [mil]
  rect 900x250 on Top Solder paste-125 mask-125: 0(0,0)
  Top Layer region: -285.35,87.97 -285.35,87.24 -285.35,86.51 -285.35,85.79 -286.07,85.79 -286.07,85.06 -286.07,84.33 -286.07,83.6 -286.07,82.88 -286.07,82.15 -286.8,82.15 -286.8,81.42 -286.8,80.7 -286.8,79.97 -286.8,79.24 -286.8,78.52 -287.53,78.52 -287.53,77.79 -287.53,77.06 -287.53,76.34 -287.53,75.61 -287.53,74.88 -288.26,74.88 -288.26,74.15 -288.26,73.43 -288.26,72.7 -288.26,71.97 -305.7,71.97 -305.7,72.7 -305.7,73.43 -304.98,73.43 -304.98,74.15 -304.98,74.88 -304.98,75.61 -304.98,76.34 -304.98,77.06 -304.25,77.06 -304.25,77.79 -304.25,78.52 -304.25,79.24 -304.25,79.97 -304.25,80.7 -303.52,80.7 -303.52,81.42 -303.52,82.15 -303.52,82.88 -303.52,83.6 -303.52,84.33 -302.8,84.33 -302.8,85.06 -302.8,85.79 -302.8,86.51 -302.8,87.24 -302.8,87.97 -302.07,87.97 -302.07,88.69 -285.35,88.69
  Top Layer region: 260 vertices and 0 holes, not listed, extent 314.43,-97.42 368.95,-39.99
  Top Layer region: 233 vertices and 0 holes, not listed, extent -189.38,-97.42 -163.21,-22.54
  Top Layer region: 259 vertices and 0 holes, not listed, extent -52.71,-97.42 1.82,-39.99
  Top Layer region: 247 vertices and 0 holes, not listed, extent -321.7,-9.45 -289.71,64.7
  Top Layer region: 372 vertices and 0 holes, not listed, extent 60.7,-98.15 121.05,-39.99
  Top Layer region: 374 vertices and 0 holes, not listed, extent 371.13,-98.15 418.39,-39.26
  Top Layer region: 380 vertices and 0 holes, not listed, extent -98.51,-98.15 -51.25,-39.26
  Top Layer region: 383 vertices and 0 holes, not listed, extent 12,-10.91 59.25,47.98
  Top Layer region: 288 vertices and 0 holes, not listed, extent -155.21,-10.18 -102.87,47.26
  Top Layer region: 288 vertices and 0 holes, not listed, extent 201.74,-97.42 254.09,-39.99
  Top Layer region: 294 vertices and 0 holes, not listed, extent -211.19,-10.18 -141.4,64.7
  Top Layer region: 493 vertices and 0 holes, not listed, extent 255.54,-98.15 313.7,-39.99
  Top Layer region: 488 vertices and 0 holes, not listed, extent -158.85,-98.15 -100.69,-39.99
  Top Layer region: 323 vertices and 1 holes, not listed, extent 3.27,-98.15 65.79,-39.99
  Top Layer region: 640 vertices and 0 holes, not listed, extent 124.68,-98.15 197.38,-39.99
  Top Layer region: 741 vertices and 1 holes, not listed, extent -104.32,-10.18 14.18,47.26
  Top Layer region: 1040 vertices and 0 holes, not listed, extent -418.39,-77.79 -237.37,98.15
TO-220V [mil]
  rect 70x70 hole 40: 1(0,0) 2(100,-100) 3(200,0)
TO-277[SMPC] [mil]
  rect 55x50 smd: 1(42,-168.6) 2(-42,-168.6)
  rect 185x195 smd: 3(0,0)
TR_SOT223 [mil]
  rect 35x80 smd: 1(-90.6,-110.9) 2(0,-110.9) 3(90.6,-110.9)
  rect 130x80 smd: 4(0,109.5)
  silkscreen extent -147,-134 -122,-109
XFMR-EI30-10PIN-VER-TEMP [mm]
  rect 3x3 hole 1.27: 1(0,0)
  round 3 hole 1.27: 2(0,-5) 3(0,-10) 4(0,-15) 5(0,-20) 6(0,-25) 7(17.5,-25) 8(17.5,-20) 9(17.5,-15) 10(17.5,-10) 11(17.5,-5) 12(17.5,0)

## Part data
B1 B2 B4 B5 B6: "FERRITE CHIP 70 OHM 4000MA 0603"
B3: library part BEAD-BLM18AG_SERIES, "FERRITE CHIP 70 OHM 4000MA 0603"
C1 C2 C5 C21: library part CAP_ECQU2A104XL, "CAP FILM 0.47UF 560VDC RADIAL"
C3 C42: "CAP CER 100PF 1KV 10% RADIAL"
C4: "CAP ALUM 33UF 450V 20% RADIAL"
C6: "CAP ALUM 68UF 450V 20% RADIAL"
C7 C8: "CAP CER 330PF 300VAC 10% RADIAL"
C9 C10 C19 C26: library part CAP_DISK_440_[8.4MM], "CAP CER 2200PF 300VAC 20% RADIAL"
C11 C20: "CAP CER 10000PF 1KV 20% RADIAL"
C12 C33: "CAP ALUM 33UF 35V 20% RADIAL"
C13 C15: "CAP CER 470PF 50V 5% NP0 0603"
C14: "CAP, CERM, 22uF, 16V, +/-10%, X5R, 0805"
C16 C24 C29 C32: "CAP CER 0.1UF 50V 10% X7R 0603"
C17: "CAP, CERM, 2200pF, 50V, +/-10%, X7R, 0603"
C18 C45: "CAP CER 1UF 25V 10% X7R 0603"
C22: "CAP CER 1000PF 500VAC 20% RADIAL"
C23 C27: "CAP CER 330PF 250V 5% NP0 0603"
C25 C31: "CAP ALUM 220UF 35V 20% RADIAL"
C28: library part 1812GC472KA1, "CAP, CERM, 4700pF, 2000V, +/-10%, X7R, 1812"
C30: "CAP ALUM 56UF 35V 20% RADIAL"
C34: "CAP CER 1000PF 250V 5% NP0 0603"
C35 C36: "CAP ALUM 470UF 35V 20% RADIAL"
C37: "CAP ALUM 220UF 25V 20% RADIAL"
C38: "CAP CERAMIC, 25V, C0G, 10%"
C39: "CAP CER 0.33UF 25V 10% X7R 0603"
C40: "CAP CER 0.022UF 50V 10% X7R 0603"
C41: "CAP CER 0.033UF 50V 10% X7R 0603"
C43: "CAP CER 330PF 50V 5% NP0 0603"
C44: "CAP CER 100PF 50V 10% NP0 0603"
C46: "CAP, CERM, 0.01uF, 1000V, +/-10%, X7R, 1210"
C47 C48 C49: "CAP, CERM, 0.068uF, 16V, +/-10%, X7R, 0603"
D1: "Diode, Utrafast, Power Rectifier, 600V, 4A"
D2 D3 D4 D5: "Diode, Rectifier, 600V, 6A"
D6: "Diode, Rectifier, 800V, 1A"
D7: "DIODE, Zener, 18V, .5W, 5%"
D8: "DIODE, Zener, 15V, .5W, 5%"
D9: "Diode, Schottky, 2-A, 80-V"
D10: "DIODE,Transient Voltage Suppressor,120V, 600W"
D11 D14: "Diode, Fast, 600V, 1A"
D12: "Diode, Rectifier, Trr 20 ns, Vrrm 200V, 3A"
D13: "Diode Schottky, 8A, 100V"
D15: "Diode, Signal, 200-mA, 100-V, 350-mW"
D16: "Diode, Schottky, 40V, 1A, SOD-123"
D17: "Diode, Signal, 300-mA, 75-V, 350-mW"
F1: "FUSE SLOW 250VAC 5A RADIAL"
FID1 FID2 FID3 FID4 FID5 FID6: "Fiducial mark.  There is nothing to buy or mount."
H1 H2 H3 H4: library part "NY PMS 440 0025 PH", "Mounting Hole M3 3.5mm"
HT1 HT2: library part HEATSINK_R2A-CT2-38E, "Heatsink, TO-220"
J1 J2: "Terminal Block, 2x1, 5.08mm, TH"
J3: "Terminal Block, 3x1, 5.08 mm, TH"
L1: "Inductor, 82uH"
L2: library part IND_SS30V-R350047, "Inductor, Power Choke SS30V"
L3: library part IND_744824622, "CHOKE TOROID 1.0mH 10A VERT"
L5: library part IND_RFB0807_SERIES, "INDUCTOR 2.2UH 4.1A RADIAL"
LBL1: library part THT-14-423-10, "Thermal Transfer Printable Labels, 0.650\" W x 0.200\" H - 10,000 per roll"
Logo1: library part TI_Logo, "Texas Instrument Corporate Signature"
Logo3 Logo4 Logo5 Logo6: library part IEC_HighVoltage, "IEC 61010-1 High Voltage Warning"
Q1: "MOSFET N-CH 600V 120MA SOT-223"
Q2: "MOSFET N-CH 600V 21MA SOT23"
Q3: "MOSFET, Nch, 600-V, 20A, 0.199 Ohms"
Q4 Q5: "MOSFET N-CH 60V 260MA SOT-23"
Q6: "MOSFET, Nch, 600-V, 4A, 0.9 Ohms"
R1: "RES 330 OHM 1W 5% 2512"
R2: "RES, 220 ohm, 1%, 0.1W, 0603"
R3 R30: "RES 44.2K OHM 1/10W 1% 0603 SMD"
R4: "RES 1.33M OHM 1/10W 1% 0603 SMD"
R5 R7 R11: "RES 649K OHM 1/4W 1% 1206 SMD"
R6 R25: "RES 30.1K OHM 1/10W 1% 0603 SMD"
R8: "RES 1.00M OHM 1/10W 1% 0603 SMD"
R9: "RES 15.0 OHM 1/8W 1% 0805 SMD"
R10: "RES, 402k ohm, 1%, 0.1W, 0603"
R12: "RES, 1.00Meg ohm, 1%, 0.1W, 0603"
R13: "RES 226 OHM 1/10W 1% 0603 SMD"
R14: "RES 348K OHM 1/10W 1% 0603 SMD"
R15: "RES 0.02 OHM 1W 1% 2512 SMD"
R16: "RES, 127k ohm, 1%, 0.1W, 0603"
R17: "RES 3.83K OHM 1/10W 1% 0603 SMD"
R18 R19: "RES 33 OHM 1W 5% 2512"
R20: "RES 301K OHM 1/10W 1% 0603 SMD"
R21: "RES 71.5K OHM 1/10W 1% 0603 SMD"
R22: "RES 1.21K OHM 1/10W 1% 0603 SMD"
R23: "RES 8.20 OHM 1/4W 1% 1206 SMD"
R24: "RES 10.5K OHM 1/10W 1% 0603 SMD"
R26: "RES 162K OHM 1/10W 1% 0603 SMD"
R27: "RES 8.20 OHM 1W 5% 2512"
R28: "RES 3.01K OHM 1/10W 1% 0603 SMD"
R29: "RES 3.65K OHM 1/10W 1% 0603 SMD"
R31: "RES 49.9 OHM 1/10W 1% 0603 SMD"
R32: library part CRCW2512332RFKEG, "RES 162 OHM 1.5W 1% 2512 SMD"
R33: "RES 1.00K OHM 1/10W 1% 0603 SMD"
R34: "RES 10.0 OHM 1/8W 1% 0805 SMD"
R35: "RES 100K OHM 1/10W 1% 0603 SMD"
R36: "RES 9.53K OHM 1/10W 1% 0603 SMD"
R37: "RES 1.62K OHM 1/10W 1% 0603 SMD"
R38: "RES 0.33 OHM 1W 1% 2010"
R39: "RES 2.49K OHM 1/10W 1% 0603 SMD"
R40: library part CRCW251222R0JNEGHP, "RES 68 OHM 2W 1% 2512"
R41: "RES, 27.0k ohm, 1%, 0.1W, 0603"
R42: "RES, 4.30k ohm, 1%, 0.1W, 0603"
RT1 RT2 RT3: "MOV, 300V"
T1: library part XFMR_750811190, "Transformer, EI-30, Vertical"
TP1 TP2 TP4 TP5 TP6 TP7 TP8 TP9: "TEST POINT.  No entry in BOM."
U1: "IC REG CTRLR BST FLYBK CM 10MSOP"
U2 U4: "IC DETECTOR UNDER VOLT 3V SC70-5"
U3: "IC REG LDO NEG ADJ 1.5A TO252"
U5: library part UCC28600D, "IC CTRLR PWM GREEN CM OVP 8SOIC"
U6: library part OPTO_PS2513-1, "OPTOCOUPLER TRANS 5KVRMS 4DIP"
U7: "IC VREF SHUNT PREC ADJ SOT23-3"

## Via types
v1: diameter 40, hole 20, Top Layer to Bottom Layer, tented both sides, 69 vias
v2: diameter 50, hole 28, Top Layer to Bottom Layer, tented both sides, 21 vias

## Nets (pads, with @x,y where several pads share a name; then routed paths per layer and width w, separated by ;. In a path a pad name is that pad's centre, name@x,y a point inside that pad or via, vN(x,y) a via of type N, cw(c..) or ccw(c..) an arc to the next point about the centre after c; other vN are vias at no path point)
AGND: B2.1 C22.1 C25.2 T1.12 | length 2032.1
  Top Layer w40: B2.1@4785,3333.5 4785,3275 v1(4800,3260) ; C22.1@4934,2045 5137.98,2248.98 T1.12@5275,2248.98
  Bottom Layer w40: v1(4800,3260) 4800,2650 4675,2525 C25.2@4675,2481 5042.98,2481 T1.12@5275,2248.98
NetB1_1: B1.1 C25.1 D9.1 R18.2 | length 1310
  Top Layer w40: B1.1@4712,3333.5 4712,3232 4675,3195 C25.1@4675,2678 4763,2678 4815,2730 4815,2775 4865,2825 R18.2@4920,2825 ; R18.2@4927,2761 4927,2628 4980,2575 D9.1@4980,2476
NetB1_2: B1.2 C24.1 J2.1 | length 348.2
  Top Layer w12: B1.2@4713.7,3393.05 B1.2@4715,3394.35
  Top Layer w40: J2.1@4660.69,3723.31 4715,3669 C24.1@4715,3481 ; B1.2@4712,3396.5 C24.1@4712,3478
NetB2_2: B2.2 C24.2 C26.1 J2.2 | length 707.5
  Top Layer w40: B2.2@4785,3396.5 C24.2@4785,3481 4785,3647.63 J2.2@4860.69,3723.31 5032.31,3723.31 C26.1@5158,3849
NetB3_1: B3.1 D11.2 Q6.2 R32.2 TP5.1 | length 545.2
  Bottom Layer w40: B3.1@6005,1273.5 D11.2@6005,1125 6005,940 R32.2@6010,935
  Bottom Layer w60: R32.2@6010,935 6081.85,935 Q6.2@6175.75,841.1
NetB3_2: B3.2 T1.4 | length 251.3
  Bottom Layer w40: T1.4@5865.55,1530 5865.55,1475.95 B3.2@6005,1336.5
NetB4_1: B4.1 C30.2 R22.2 TP6.1 U3.3 | length 2362
  Top Layer w25: R22.2@5700,3480 R22.2@5705,3485
  Top Layer w30: U3.3@5544,3480 5700,3480 R22.2@5705,3480 ; R22.2@5705,3485 5705,3662.5 C30.2@5717.5,3675
  Top Layer w40: B4.1@7330,3241.5 v1(7330,3310)
  Bottom Layer w60: C30.2@5717.5,3675 5717.5,3597.5 5765,3550 6480,3550 6566.2,3636.2 7088.8,3636.2 7330,3395 v1(7330,3310)
NetB4_2: B4.2 C29.1 J3.1 | length 327.6
  Top Layer w30: B4.2@7330,3178.5 7335,3173.5 C29.1@7335,3110 7390,3110 7430.31,3150.31 J3.1@7575.31,3150.31
NetB5_2: B5.2 C28.2 C29.2 C32.1 J3.2 | length 694.3
  Top Layer w30: B5.2@7249.5,3042 7398,3042 v2(7400,3040)
  Bottom Layer w30: C32.1@7336,2976 v2(7400,3040) ; 7400,3280 v2(7400,3040) ; J3.2@7575.31,2950.31 7485.63,3040 v2(7400,3040)
NetB6_1: B6.1 C37.1 L5.2 R28.1 R31.2 TP7.1 | length 1181.4
  Top Layer w20: R31.2@7345,2405 7540,2405 7580,2445 TP7.1@7580,2510
  Top Layer w30: v1(7195,2760) 7195,2705 7265,2635 R28.1@7265,2455 7295,2455 R31.2@7345,2405
  Bottom Layer w20: 6941,2944 6975,2910 B6.1@7203.5,2910
  Bottom Layer w30: v1(7195,2760) 7195,2901.5 B6.1@7203.5,2910
NetB6_2: B6.2 C32.2 J3.3 | length 354.8
  Bottom Layer w30: B6.2@7285,2906 C32.2@7336,2906 7419.63,2906 J3.3@7575.31,2750.31
NetC1_1: C1.1 C8.1 J1.2 L3.2 RT1.1 RT2.2 | length 2460.1
  Top Layer w40: C8.1@487,926 546,985 C1.1@915,985 915,845 RT1.1@1072.5,687.5
  Top Layer w60: C1.1@915,985 915,1296 L3.2@978,1359 ; J1.2@915.32,269.69 915.32,530.32 RT1.1@1072.5,687.5
  Bottom Layer w40: RT2.2@472.5,622.5 472.5,911.5 C8.1@487,926 546,985 C1.1@915,985
NetC1_2: C1.2 C7.1 F1.2 L3.4 RT1.2 RT3.2 | length 3937.9
  Top Layer w40: RT3.2@447.5,1267.5 447.5,1496.5 C7.1@487,1536 551,1600 1293,1600 1372,1521 L3.4@1372,1359
  Top Layer w60: 1368,667 1368,597 ; L3.4@1372,1359 1372,1254 1505,1121 C1.2@1505,985 1505,852 1367.5,714.5 1367.5,597.5 1368,597 ; F1.2@1415,405 1368,452 1368,597
  Bottom Layer w40: RT3.2@447.5,1267.5 447.5,1496.5 C7.1@487,1536 551,1600 1293,1600 1372,1521 L3.4@1372,1359
NetC2_1: C2.1 C10.1 L2.4 L3.9 | length 1466.6
  Bottom Layer w40: C10.1@487,2241 546,2300 C2.1@885,2300 885,2696.93 L2.4@765,2816.93 ; C2.1@885,2270 885,1924 L3.9@978,1831
NetC2_2: C2.2 C9.1 L2.3 L3.7 | length 2197.5
  Top Layer w40: C9.1@487,1921 651,2085 1015,2085 1230,2300 C2.2@1475,2300
  Bottom Layer w80: L3.7@1372,1831 1475,1934 C2.2@1475,2300 1475,2759.21 L2.3@1532.72,2816.93
NetC3_1: C3.1 C6.1 C19.1 C20.2 C21.2 C22.2 D1.1 D10.2 Q1.2 Q1.4 R5.1 T1.1 TP4.1 | length 5996.2
  Top Layer w40: v2(4070,255) 4475,660 C21.2@4475,794
  Top Layer w60: C21.2@4475,794 4526,794 ; 4640,680 4526,794 ; C22.2@4805.38,1661.24 4946.62,1520 5265,1520 C20.2@5265,1345 5262,1348 5158,1348 D10.2@4975,1165 ; D10.2@4960,1150 D10.2@4975,1165 ; 4526,794 4531.1,794 C6.1@4900,425.1 4975,500.1 D10.2@4975,1165
  Bottom Layer w25: R5.1@3615,105 4036.5,105 4070,138.5 v2(4070,255) ; Q1.2@3754.1,280 Q1.4@3974.5,280
  Bottom Layer w50: Q1.4@3974.5,280 4045,280 v2(4070,255)
  Bottom Layer w60: C21.2@4475,794 4546,865 C3.1@4815,865 ; T1.1@5275,1530 5275,1550 5515,1790 6509,1790 C19.1@6554,1745
NetC3_2: C3.2 R1.2 | length 325.2
  Bottom Layer w60: R1.2@4635,1260 4730,1260 4815,1175 C3.2@4815,1065
NetC4_1: C4.1 C5.2 D2.1 D3.1 D6.2 L1.6 L1.7 L1.8 TP1.1 | length 2718.6
  Top Layer w40: C4.1@2400.6,2076.6 2400.6,1764.4 2570,1595 D6.2@2570,1495
  Top Layer w100: v1(2670.32,2545) D3.1@2670.32,2701.5 ; v1(2795,2805) v1(2955,2805) ; v1(2855,2545) 3010,2545 v1(3015,2550)
  Bottom Layer w100: C4.1@2400.6,2076.6 2670.32,2346.32 v1(2670.32,2545) ; D3.1@2670.32,2701.5 v1(2670.32,2545) ; v1(2795,2805) 2855,2745 v1(2855,2545) v1(2670.32,2545) ; v1(2955,2805) v1(3180,2805) ; v1(3015,2550) 3020,2555 v1(3170,2555)
NetC7_2: C7.2 C8.2 C9.2 C10.2 H2.1 RT2.1 RT3.1
NetC11_2: C11.2 D6.1 Q2.3 | length 379.4
  Top Layer w20: D6.1@2170,1495 D6.1@2180,1485
  Top Layer w25: C11.2@2005,1355 2047.6,1312.4 Q2.3@2180,1312.4 D6.1@2180,1485
NetC12_1: C12.1 C45.2 C47.1 D7.1 D15.1 R2.1 R3.2 R4.1 TP2.1 U1.10 U5.6 | length 8631.1
  Top Layer w25: D7.1@2320,175 2410.5,265.5 C12.1@2640,265.5 ; C12.1@2639,254 2640,255 2775,120 3040,120 3090,170 v2(3190,170) 3226.5,133.5 4233.5,133.5 4375,275 4555,275 4665,165 7131.5,165 D15.1@7538.5,572 ; v1(7040,715) 7070,685 C45.2@7070,655 7455.5,655 D15.1@7538.5,572 ; TP2.1@7685,570 7540.5,570 D15.1@7538.5,572
  Top Layer w40: C12.1@2640,265.5 2714.5,340 2910,340 2950,380 2950,550 2755,745 v2(2755,781)
  Bottom Layer w12: U1.10@2673.8,781 v2(2755,781)
  Bottom Layer w15: v2(3190,170) 3204.5,184.5 3462.76,184.5 3502.56,224.3 R3.2@3621.57,224.3
  Bottom Layer w25: C47.1@2565,241.5 2616,241.5 C12.1@2640,265.5 ; v2(3190,170) 3145,170 3123,192 3123,303 3190,370 R2.1@3580,370 ; v1(7040,715) 7060,735 U5.6@7060,801
  Bottom Layer w30: R4.1@2755,720 v2(2755,781)
NetC13_2: C13.2 R4.2 U1.1 | length 283.6
  Bottom Layer w10: U1.1@2673.8,610 2695,610 2705,600
  Bottom Layer w20: 2705,600 2715,590 2815,590 2825,600 C13.2@2825,640 R4.2@2825,720
NetC14_1: C14.1 U1.2 | length 169.6
  Bottom Layer w10: U1.2@2654.1,610 2654.1,570.66 2673.76,551 2700,551 2715,536 C14.1@2715,481
NetC15_1: C15.1 C16.2 R11.2 R17.1 U1.5 | length 484
  Bottom Layer w10: 2550,551 2580,551 2595,566 U1.5@2595,610
  Bottom Layer w12: 2570,610 U1.5@2595,610
  Bottom Layer w25: R11.2@2405,336 2450,381 C16.2@2450,426 C15.1@2450,501 2450,510 2491,551 2550,551 ; R17.1@2520,600 2560,600 2570,610
NetC15_2: C15.2 D17.2 R14.1 U1.4 | length 785.6
  Top Layer w20: v1(2350,650) 2570,430 v1(2655,430)
  Bottom Layer w10: R14.1@2600,456 2600,536 2614.7,550.7 U1.4@2614.7,610
  Bottom Layer w20: v1(2350,650) D17.2@2350,715 ; C15.2@2520,501 2545,501 2590,456 R14.1@2600,456 2629,456 v1(2655,430)
NetC16_1: C16.1 R14.2 | length 96.6
  Bottom Layer w20: C16.1@2520,426 2560,426 R14.2@2600,386
NetC17_2: C17.2 D16.1 R13.1 U1.7 | length 361.3
  Top Layer w20: D16.1@2434.47,890 2484.47,840 v1(2520,840)
  Bottom Layer w10: C17.2@2600,895 2600,830 2614.7,815.3 U1.7@2614.7,781
  Bottom Layer w20: v1(2520,840) R13.1@2520,895 C17.2@2600,895
NetC18_2: C18.2 R41.2 U1.9 | length 264.5
  Bottom Layer w10: U1.9@2654.1,781 2654.1,814.1 2675,835 2735,835 2755,855 C18.2@2755,895 2746.5,903.5 R41.2@2685,903.5
NetC20_1: C20.1 D10.1 D11.1 | length 431.1
  Top Layer w40: C20.1@5465,1345 D10.1@5660,1150 5780,1150 D11.1@5805,1125
NetC23_1: C23.1 D9.2 T1.11 | length 557
  Top Layer w40: C23.1@5160,2620 5155,2615 D9.2@5155,2476 5241,2390 5330.83,2390 T1.11@5471.85,2248.98
NetC23_2: C23.2 R18.1 | length 139.1
  Top Layer w40: C23.2@5160,2690 5160,2815 R18.1@5170,2825
NetC26_2: C26.2 C28.1 H3.1 | length 2530.3
  Top Layer w60: H3.1@7608.74,3673.74 H3.1@7640,3705
  Bottom Layer w60: C26.2@5532.5,3686 C26.2@5532.5,3691 5532.5,3762.5 5630,3860 7285,3860 7455,3690 7625,3690 C28.1@7625,3483.74
NetC27_1: C27.1 C31.2 D12.2 U3.2 U3.4 | length 911.6
  Top Layer w30: C27.1@5495,2755 5655,2755 D12.2@5675,2735 5675,2905 5621,2959 5621,3045 5621,3344 5585,3380 U3.2@5544,3380
NetC27_2: C27.2 R19.1 | length 350.7
  Top Layer w30: v1(5495,2605) C27.2@5495,2685
  Bottom Layer w30: v1(5495,2605) 5495,2680 5545,2730 R19.1@5670,2730
NetC33_1: C33.1 D14.2 D15.2 R21.2 | length 1604.4
  Top Layer w25: C33.1@6604.5,1335 6470,1200.5 D14.2@6470,1125 6640,1125 6770,1255 7350,1255 D15.2@7533,1072
  Bottom Layer w20: R21.2@7397,1061 7461,1061 7472,1072 D15.2@7538.5,1072
NetC34_1: C34.1 R27.1 | length 211.9
  Bottom Layer w30: C34.1@6278,2519 6353,2519 6418,2454 R27.1@6463,2454
NetC34_2: C34.2 D13.1 D13.2 T1.7 | length 189.8
  Top Layer w30: v1(6195,2490) 6245,2440 6260,2440
  Bottom Layer w30: v1(6195,2490) 6246,2439 C34.2@6278,2439
NetC35_1: C35.1 C36.1 D13.3 L5.1 R27.2 R29.2 | length 1609.1
  Top Layer w30: D13.3@6445,2625 6445,2823 C36.1@6318,2950 6318,3415 C35.1@6313,3420 L5.1@6530,3420
  Bottom Layer w40: C36.1@6318,2950 6468,2800
  Bottom Layer w50: R27.2@6453,2710 6685,2710 6705,2730 6775,2730
NetC38_1: C38.1 R26.2 R30.1 U5.7 | length 1097.5
  Top Layer w20: v1(6980,720) 6980,710 6990,700 C38.1@6990,655
  Bottom Layer w20: v1(6980,720) 7010,750 U5.7@7010,801
  Bottom Layer w25: R26.2@6445,1325 6445,1265 6525,1185 6595,1185 R30.1@6660,1120 6660,925 6865,720 v1(6980,720)
NetC39_1: C39.1 C41.2 R36.2 R39.1 U7.2 | length 985.5
  Top Layer w25: v1(7045,2215) 7120,2215 7210,2305 R36.2@7265,2305 R39.1@7265,2380
  Bottom Layer w25: U7.2@6858.4,2580.6 6933.4,2580.6 C41.2@6935,2579 6935,2470 6900,2435 6900,2245 6930,2215 v1(7045,2215) C39.1@7045,2285
NetC39_2: C39.2 R35.2 | length 148.8
  Bottom Layer w25: C39.2@6975,2285 6977,2287 R35.2@6977,2433
NetC40_2: C40.2 U5.1 | length 169.4
  Bottom Layer w20: C40.2@6865,1120 6960,1025 U5.1@6960,990
NetC41_1: C41.1 R33.2 R35.1 U6.2 U7.1 | length 1276.8
  Bottom Layer w25: U7.1@6858.4,2655.4 6928.6,2655.4 6934,2650 6982,2650 7008,2624 R33.2@7008,2576 7008,2516 7047,2477 R35.1@7047,2433 7047,2393 7135,2305 7135,2120 6949,1934 U6.2@6949,1639.5
NetC42_1: C42.1 R32.1 | length 349.9
  Bottom Layer w60: C42.1@5415,935 R32.1@5764.92,935
NetC43_1: C43.1 TP9.1 U5.2 U6.4 | length 581.7
  Bottom Layer w25: U5.2@7010,990 7010,1076 6966,1120 C43.1@6945,1120 6974,1120 7005,1151 7005,1295.5 U6.4@7049,1339.5 7053.5,1335 TP9.1@7180,1335
NetC44_1: C44.1 R37.1 U5.3 | length 215
  Bottom Layer w20: U5.3@7060,990 C44.1@7060,1120 R37.1@7145,1120
NetC46_1: C46.1 R40.1 | length 129.9
  Bottom Layer w50: C46.1@3195,1600 R40.1@3324.92,1600
NetC48_1: C48.1 R10.2 R12.1 R16.1 U2.5 | length 918.8
  Top Layer w10: R12.1@2277,398 R12.1@2277.9,398.9
  Top Layer w15: R12.1@2277.9,398.9 U2.5@2277.9,489.4 2277.9,490.9 v2(2317,530)
  Top Layer w25: v2(2280,969.5) R16.1@2223,969.5 2223,1006 2213,1016 ; C48.1@2288.5,1050 R10.2@2213,1050 ; 2213,1016 R10.2@2213,1050 ; 2213,1016 2211.5,1017.5 R10.2@2211.5,1050 R10.2@2213,1050
  Bottom Layer w25: v2(2280,969.5) 2205,894.5 2205,642 v2(2317,530)
NetC49_1: C49.1 R20.1 R21.1 R25.1 U4.5 | length 558.5
  Bottom Layer w12: R20.1@7336,617 7338.1,619.1 U4.5@7338.1,703.4 7338.1,731.9 7351.2,745 7422.2,745 7445,767.8 7445,835 R25.1@7397,883 ; R21.1@7397,991 R25.1@7397,883 ; C49.1@7472.01,890 7404,890 R25.1@7397,883
NetD1_2: D1.2 L1.3 L1.4 L1.5 Q3.2 R1.1 R40.2 | length 1028.2
  Top Layer w50: L1.4@3480.08,1384.92 L1.4@3485,1380 ; Q3.2@3485,934.1 L1.4@3485,1380 ; L1.4@3490,1385 L1.4@3485,1380 ; D1.2@4490,1775 D1.2@4495,1770
  Bottom Layer w50: L1.4@3490,1385 3565.08,1460.08 R40.2@3565.08,1590 ; D1.2@4490,1775 4635,1630 R1.1@4635,1510
NetD2_2: D2.2 D4.1 L2.1 | length 2050.3
  Top Layer w80: v1(3965,3440) 3970,3435 v1(4110,3435) ; v1(3975,2620) 3980,2625 v1(4125,2625) ; v1(3980,2780) v1(3980,2915) ; v1(3980,3075) v1(3980,3230) ; v1(4110,3250) 4115,3255 v1(4115,3075) ; v1(4115,2780) v1(4115,2915)
  Bottom Layer w80: D4.1@3674,3213.31 3963.31,3213.31 v1(3980,3230) ; v1(3975,2620) 3980,2625 v1(3980,2780) ; v1(3980,2915) v1(3980,3075) ; v1(4110,3250) v1(4110,3435) ; v1(4115,2780) 4125,2770 v1(4125,2625) ; v1(4115,2915) v1(4115,3075)
NetD3_2: D3.2 D5.1 L2.2 | length 2712.1
  Top Layer w20: v1(1530,3365) 1532.72,3362.28 L2.2@1532.72,3250 L2.2@1537.72,3245 ; v1(1775,3245) L2.2@1537.72,3245 ; v1(1775,3525) 1785,3535 v1(2055,3535) ; v1(1785,3115) 1667.72,3115 L2.2@1537.72,3245 ; v1(1785,3365) 2050,3365 v1(2060,3375) ; v1(1885,2975) 1890,2970 v1(2075,2970) v1(2075,2855)
  Bottom Layer w20: v1(1530,3365) 1530,3445 v1(1600,3515) ; L2.2@1532.72,3250 1537.72,3245 v1(1775,3245) ; v1(1775,3525) 1775,3375 v1(1785,3365) ; v1(1785,3115) 1785,3075 v1(1885,2975) ; v1(2060,3375) 2070,3365 D5.1@2070,3213.31 2070,2975 v1(2075,2970)
NetD8_1: D8.1 Q2.1 R6.2 R8.1 R10.1 | length 402.7
  Top Layer w25: D8.1@2010,1050 R10.1@2143,1050 ; R8.1@2142,973 2148.5,979.5 R10.1@2148.5,1050 2145,1053.5 R6.2@2145,1140 2145,1235.2 Q2.1@2142.6,1237.6
NetD12_1: D12.1 R19.2 T1.10 | length 440.2
  Top Layer w50: T1.10@5668.7,2248.98 5675,2255.28 D12.1@5675,2455
  Bottom Layer w50: T1.10@5668.7,2248.98 5670,2250.28 R19.2@5670,2480
NetD14_1: D14.1 R23.2 R26.1 | length 316.2
  Bottom Layer w25: D14.1@6270,1125 6270,1220 6275,1225 R23.2@6275,1335 6325,1335 6335,1325 R26.1@6375,1325
NetD17_1: D17.1 R41.1 R42.2 | length 762.6
  Bottom Layer w15: R41.1@2685,966.5 R42.2@2755,966.5
  Bottom Layer w20: D17.1@2350,845 2350,965 2500,1115 2685,1115 2725,1075 2725,1003.5 R42.2@2758.5,970
NetF1_1: F1.1 J1.1
NetQ1_1: Q1.1 Q5.3 R3.1 | length 308.7
  Bottom Layer w20: Q5.3@3537.4,285 3576.57,285 3585.87,294.3 R3.1@3621.57,294.3 3670.7,294.3 3685,280 3685,278.76 3684.1,277.86 3684.1,205.9 3700.6,189.4 Q1.1@3754.1,189.4
NetQ1_3: Q1.3 R2.2 | length 107.9
  Bottom Layer w20: R2.2@3646.5,370 3647.1,370.6 Q1.3@3754.1,370.6
NetQ2_2: Q2.2 R6.1 | length 98.6
  Top Layer w25: R6.1@2215,1140 2215,1235.2 Q2.2@2217.4,1237.6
